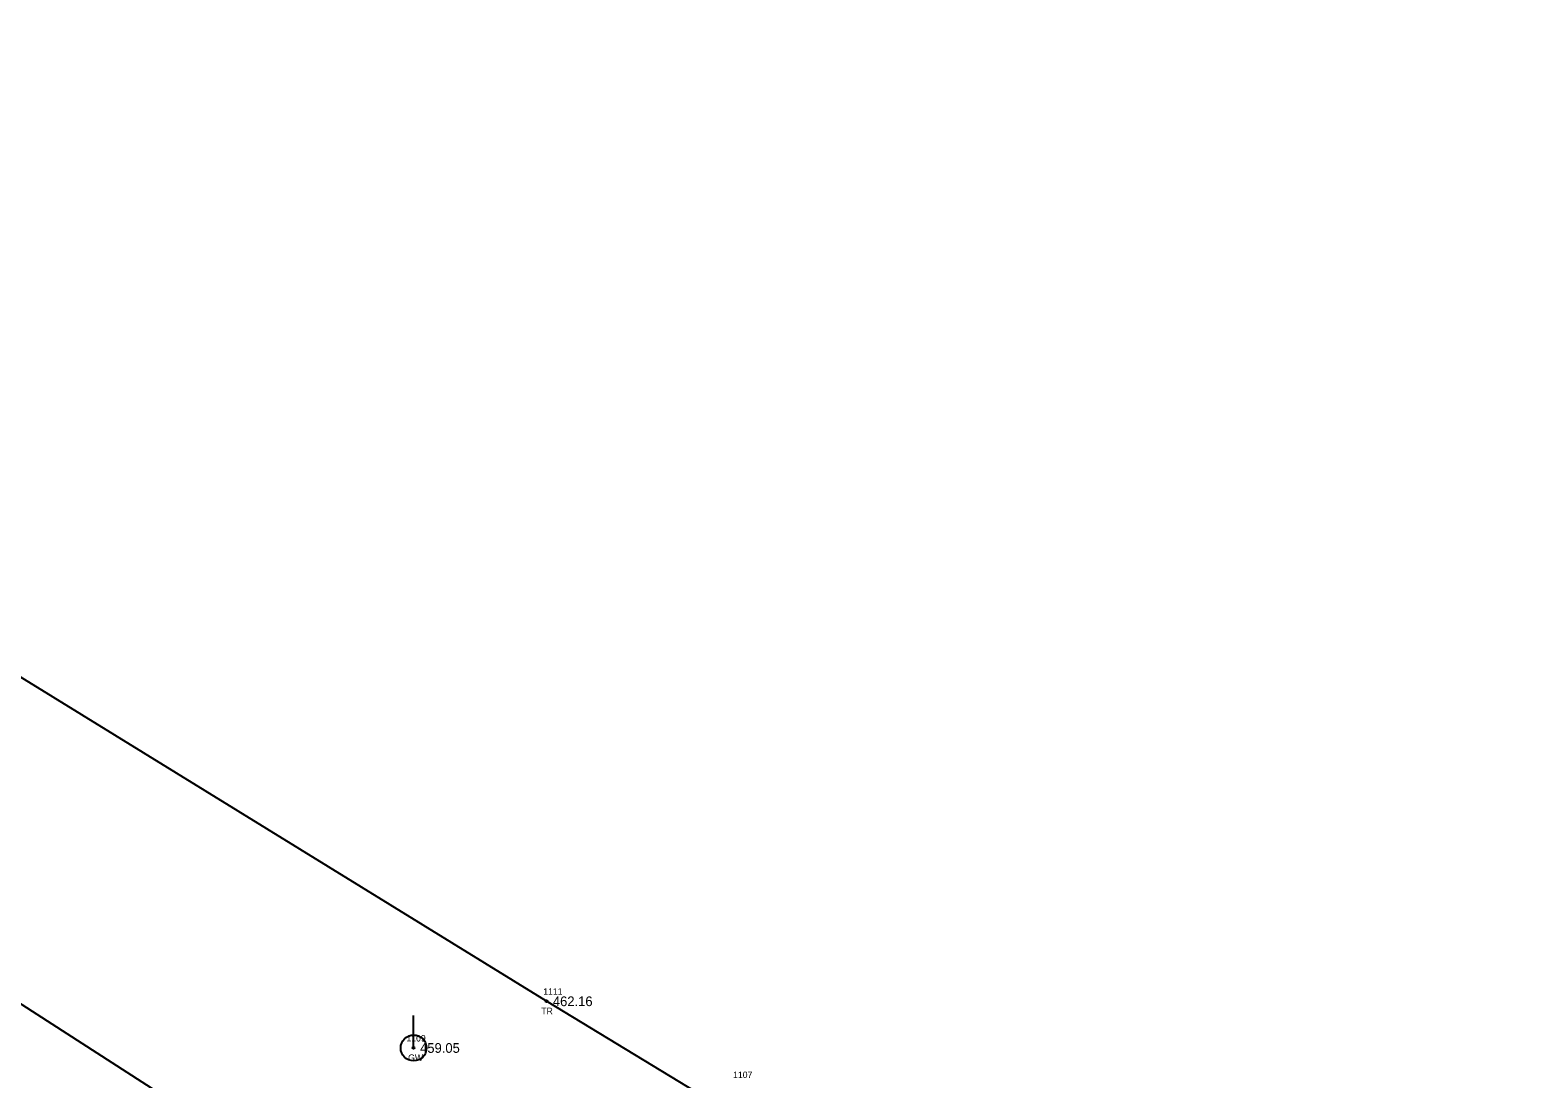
# Model space of a CAD drawing. Extents: x 1796360 to 1799195, y 895805 to 899730.
# Drawn here: x 1798789.4 to 1799022.3, y 896216.1 to 896378.1 of the extents above; entities that cross this region are included whole.
import ezdxf

# ---------------------------------------------------------------- set-up
doc = ezdxf.new("R2010")
doc.units = 0
for name, color, linetype in [('RD_EX_Fence_Other_txCode', 7, 'Continuous'), ('RD_EX_Road', 7, 'Continuous'), ('RD_EX_TX_UT_ELEV', 7, 'Continuous'), ('RD_EX_TX_VEG_ELEV', 7, 'Continuous'), ('RD_EX_UT', 7, 'Continuous'), ('RD_EX_UT_txCode', 7, 'Continuous'), ('RD_EX_VEG', 7, 'Continuous'), ('RD_EX_VEG_txCode', 7, 'Continuous'), ('RD_SMD_Locator', 7, 'Continuous')]:
    doc.layers.add(name, color=color, linetype=linetype)

msp = doc.modelspace()

# ---------------------------------------------------------------- linework, layer by layer
at = {"layer": 'RD_EX_Road'}
msp.add_lwpolyline([(1799016.83, 896078.37), (1798931.94, 896134.3), (1798843.73, 896191.67), (1798753.3, 896249.87), (1798664.51, 896307.9), (1798573.47, 896367.69), (1798486.82, 896425.22), (1798405.79, 896479.79), (1798400.67, 896472.53)], dxfattribs=at)
at = {"layer": 'RD_EX_UT'}
msp.add_line((1798848.6, 896220.83), (1798848.6, 896225.83), dxfattribs=at)
msp.add_circle((1798848.6, 896220.83), 2, dxfattribs=at)
at = {"layer": 'RD_EX_VEG'}
msp.add_lwpolyline([(1799022.27, 896088.33), (1798937.86, 896144.41), (1798896.41, 896211.5), (1798869.11, 896228.04), (1798778.26, 896284.04), (1798691.36, 896345.52), (1798595.8, 896403.96), (1798518.88, 896459.81), (1798399.83, 896534.95), (1798299.84, 896602.99), (1798218.96, 896659.85), (1798132.31, 896718.94), (1798044.28, 896770.93), (1797952.52, 896827.83), (1797861.07, 896893.41), (1797773.58, 896947.34)], dxfattribs=at)
at = {"layer": 'RD_SMD_Locator'}
for centre in [(1798869.11, 896228.04), (1798848.6, 896220.83)]:
    msp.add_circle(centre, 0.15, dxfattribs=at)

# ---------------------------------------------------------------- texts
at = {"layer": 'RD_EX_Fence_Other_txCode'}
msp.add_text('1107', height=1, dxfattribs=at).set_placement((1798897.95, 896216.18))
at = {"layer": 'RD_EX_TX_UT_ELEV'}
msp.add_text('459.05', height=1.5, dxfattribs=at).set_placement((1798849.6, 896220.08))
at = {"layer": 'RD_EX_TX_VEG_ELEV'}
msp.add_text('462.16', height=1.5, dxfattribs=at).set_placement((1798870.11, 896227.29))
at = {"layer": 'RD_EX_UT_txCode'}
for s, p in [('1109', (1798847.49, 896221.83)), ('GW', (1798847.75, 896218.83))]:
    msp.add_text(s, height=1, dxfattribs=at).set_placement(p)
at = {"layer": 'RD_EX_VEG_txCode'}
for s, p in [('1111', (1798868.62, 896229.04)), ('TR', (1798868.32, 896226.04))]:
    msp.add_text(s, height=1, dxfattribs=at).set_placement(p)

doc.saveas('drawing.dxf')
